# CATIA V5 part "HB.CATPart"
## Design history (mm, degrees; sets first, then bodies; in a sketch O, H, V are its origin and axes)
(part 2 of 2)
Body1 (main body), material "Aluminium Grey"
  Plane10: type Offset, RefPlane zx-plane, Offset 750
  DatumCurve100 to DatumCurve106
  Sketch13 on Plane10, origin (0, 750, 0), H (-1, 0, 0), V (0, 0, 1)
    projected circle E1 centre (845.606, 208.1688) radius 251.3368 from edge of DatumCurve100
    projected arc E2 centre (845.606, 208.1688) radius 251.3368 from (594.2692, 208.1688) to (704.7658, 0) ccw from edge of DatumCurve100
    projected arc E3 centre (845.606, 208.1688) radius 251.3368 from (986.4462, 0) to (594.2692, 208.1688) ccw from edge of DatumCurve100
    projected line E4 (-1750, 0) -> (1250, 0) from edge of DatumCurve101
    projected circle E5 centre (-1402.6201, 208.1688) radius 251.3368 from edge of DatumCurve102
    projected arc E6 centre (-1402.6201, 208.1688) radius 251.3368 from (-1261.78, 0) to (-1230.798, 24.7366) ccw from edge of DatumCurve102
    projected arc E7 centre (-1402.6201, 208.1688) radius 251.3368 from (-1213.9619, 374.2358) to (-1376.9419, 458.1904) ccw from edge of DatumCurve102
    projected arc E8 centre (-831.0348, -15069.2644) radius 15448.2469 from (493.1505, 322.1249) to (-1213.9619, 374.2358) ccw from edge of DatumCurve103
    projected arc E9 centre (1589.552, -12678.1554) radius 13467.1328 from (1187.0274, 782.9605) to (-1376.9419, 458.1904) ccw from edge of DatumCurve104
    projected line E10 (353.7012, 97.7708) -> (493.1505, 322.1249) from edge of DatumCurve105
    projected arc E11 centre (-2835.5431, 52064.8447) radius 52064.8447 from (-1230.798, 24.7366) to (353.7012, 97.7708) ccw from edge of DatumCurve106
    line L1 (704.7658, 0) -> (-1261.78, 0)
  Point171: (0, -50, 0), relative to vertex [element of Sketch13 | element of Sketch13]
  Point172: (0, -26, 0), relative to vertex [element of Sketch13 | element of Sketch13]
  DatumCurve107 to DatumCurve114
  Point173: (-24, 0, 0), relative to vertex [face of Corner45 | face of Curve64]
  Point174: (27, 6, 75), relative to Point165
  Curve74: Elements (Point174; Point167)
  Curve75: Elements (Point174; Point163)
  Corner50: Element1 Curve74, Element2 Curve75, Radius 48, Direction (0, 0, 1)
  Point175: type OnCurve, Support Corner45, Ratio 0.63
  Point176: type OnCurve, Support Corner45, Ratio 0.94
  Curve76: Elements (Point176; Point163)
  Curve77: Elements (Point175; Point167)
  Split8: ToCut Corner45, Cutting Point176
  Split9: ToCut Project6, Cutting Point148
  Fill43: Boundary ({project ToProject DatumCurve23, Support Plane10, Direction DatumCurve83}; Split8; Curve77; Corner50; Curve76; {split ToCut Corner45, Cutting Point176}; Curve66; Split9)
  Symmetry37: ToTransfor Fill43, Reference zx-plane
  Point177: (-42, 30, 0), relative to Point141
  DatumPoint4
  Point178: (-60, 0, 0), relative to DatumPoint4
  DatumPoint5
  Point179: (-60, 0, 0), relative to DatumPoint5
  Point180: (-40, 7, 2), relative to Point28
  Line35: type PtPt, FirstPoint Point177, SecondPoint Point178
  Line36: type PtPt, FirstPoint Point178, SecondPoint Point179
  Corner51: Element1 Line36, Element2 Line35, Radius 48, Direction (0, 0, 1)
  DatumCurve115
  Point181: type OnCurve, Support DatumCurve115, Ratio 0.59
  Point182: (-46, 0, 0), relative to Point181
  Curve78: Elements (Point180; Point182; Point179)
  Point183: (31, 0, -20), relative to vertex of DatumCurve17
  Curve79: Elements (Point183; Point180)
  Point184: (-31, 0, 33), relative to Point170
  Curve80: Elements (Point183; Point184; Point170)
  Line37: type PtPt, FirstPoint Point168, SecondPoint Point177
  Fill44: Boundary (Line37; Corner49; Curve80; Curve79; Curve78; Corner51)
  Symmetry38: ToTransfor Fill44, Reference zx-plane
  Line38: type PtPt, FirstPoint Point141, SecondPoint Point177
  Line39: type PtPt, FirstPoint Point168, SecondPoint Point141
  Fill45: Boundary (Line37; Line38; Line39)
  Point185: type OnCurve, Support Corner48, Ratio 0.47
  Point186: (-32, 31, -24), relative to Point185
  Point187: (-32, 31, -16), relative to Point161
  Point188: (-32, 31, -3), relative to Point160
  Point189: (-32, 0, 0), relative to Point159
  Curve81: Elements (Point186; Point187; Point188)
  Curve82: Elements (Point189; Point188)
  Corner52: Element1 Curve82, Element2 Curve81, Radius 62, Direction (0, 0, 1)
  Line40: type PtPt, FirstPoint Point159, SecondPoint Point189
  Line41: type PtPt, FirstPoint vertex [face of Curve70 | face of Corner48], SecondPoint vertex [face of Curve81 | face of Corner52]
  Line42: type PtPt, FirstPoint Point186, SecondPoint Point185
  MultiSel8
  Corner53: Element1 {symmetry ToTransfor Corner52, Reference zx-plane}, Element2 Corner52, Radius 500, Direction (0, 0, 1)
  DatumCurve116 to DatumCurve128
  Fill46: Boundary (Corner48; Line41; DatumCurve117; DatumCurve118; DatumCurve119; DatumCurve120; DatumCurve121; {symmetry ToTransfor Line41, Reference zx-plane}; DatumCurve124)
  Fill47: Boundary ({fillboundary BoundaryWire edge of Fill46, Support Fill46}; DatumCurve126; Line42; DatumCurve116)
  Symmetry39: ToTransfor Fill47, Reference zx-plane
  Join10: Elements (Fill47; Fill46; Symmetry39)
  Join11: Elements (edge of Fill46; edge of Fill46; edge of Fill46; edge of Fill46; edge of Symmetry39; edge of Fill46; edge of Fill47)
  Extrapol3: ToExtrapol Join11, Support Join10, Length 34
  Symmetry40: ToTransfor Fill45, Reference zx-plane
  Point190: type OnCurve, Support Corner44, Ratio 0.1935
  Symmetry41: ToTransfor Point190, Reference zx-plane
  Split10: ToCut Corner44, Cutting Point190
  Split11: ToCut Split10, Cutting Symmetry41
  Point191: (-37, 30, 40), relative to Symmetry41
  Point192: (-37, 22, 75), relative to Symmetry29
  Point193: type OnCurve, Support Split11, Ratio 0.5
  Point194: (-50, 0, 100), relative to Point193
  Symmetry42: ToTransfor Point192, Reference zx-plane
  Symmetry43: ToTransfor Point191, Reference zx-plane
  Curve83: Elements (Point191; Point192; Point194; Symmetry42; Symmetry43)
  Line43: type PtPt, FirstPoint Point190, SecondPoint Symmetry43
  Line44: type PtPt, FirstPoint Symmetry41, SecondPoint Point191
  Fill48: Boundary (Split11; Line44; Curve83; Line43)
  Join12: Elements (Symmetry38; Fill44)
  Join13: Elements (edge of Fill44; edge of Fill44; edge of Fill44; edge of Symmetry38; edge of Symmetry38; edge of Symmetry38)
  Point195: (17, 0, 101), relative to Point188
  Point196: (21, 0, 115), relative to Point189
  Symmetry44: ToTransfor Point195, Reference zx-plane
  Curve84: Elements (Point186; Point195; Point196; Symmetry44; vertex of Join11)
  Fill49: Boundary (Join11; Curve84)
  Point197: (-69, 20, 0), relative to vertex [face of Curve74 | face of Corner50]
  Point198: (-51, 20, 0), relative to vertex [face of Corner50 | face of Curve75]
  Point199: (-36, 20, 4), relative to Point167
  Curve85: Elements (Point175; Point199; Point197)
  Point200: (-45, 20, 0), relative to Point163
  Point201: (-62, 20, 0), relative to vertex [face of Corner50 | face of Curve75]
  Curve86: Elements (Point176; Point200; Point201)
  Corner54: Element1 Curve85, Element2 Curve86, Radius 56, Direction (0, 0, 1)
  Fill50: Boundary ({fillboundary BoundaryWire edge of Fill42}; {fillboundary BoundaryWire edge of Fill42}; Corner54)
  Symmetry45: ToTransfor Fill50, Reference zx-plane
  Fill51: Boundary (Corner50; Curve77; Corner54; Curve76)
  Symmetry46: ToTransfor Fill51, Reference zx-plane
  RectPattern1: of Extrapol3, direction 1 instances 5, spacing 22, along Z axis
  Join14: Elements (Fill42; Fill41; Symmetry34)
  Split12: ToCut RectPattern1, Cutting Join14
  Sketch14 on Plane9, origin (0, 0, 0), H (-1, 0, 0), V (0, 0, 1)
    line L1 (-1893.9288, 231.778) -> (-1872.7429, 355.2953)
  RectPattern2: of Join12, direction 1 instances 5, spacing 18, along Sketch14.L1 reversed
  Fill52: Boundary (edge of Fill43; edge of Fill51; edge of Fill51; edge of Fill43; edge of Fill43; {fillboundary BoundaryWire edge of Fill50, Support Fill50}; edge of Fill50)
  Symmetry47: ToTransfor Fill52, Reference zx-plane
  Plane11: type Offset, RefPlane yz-plane, Offset -1983, reversed
  Sketch15 on Plane11, origin (1983, 0, 0), H (0, 1, 0), V (0, 0, 1)
    arc A1 centre (579.7144, -6029.5397) radius 6143.2661 from (348.4449, 109.3717) to (631.5314, 113.5079) cw
    arc A2 centre (578.747, -7048.2125) radius 7181.3825 from (337.5808, 129.1194) to (658.2496, 132.7299) cw
    arc A3 centre (498.876, -4576.5398) radius 4728.1195 from (331.838, 148.6282) to (667.528, 148.5708) cw
    arc A4 centre (459.6706, -4602.659) radius 4771.8397 from (330.2171, 167.4244) to (670.7479, 164.51) cw
    arc A5 centre (67.7258, -10855.4937) radius 11063.6268 from (371.8413, 203.9526) to (666.0962, 191.94) cw
    arc A6 centre (371.2568, 313.1531) radius 109.2021 from (340.512, 208.3683) to (371.8413, 203.9526) ccw
    arc A7 centre (1244.1204, 15142.2871) radius 14945.9617 from (378.9979, 221.3845) to (655.0631, 207.938) ccw
    arc A8 centre (381.8374, 303.895) radius 82.5593 from (378.9979, 221.3845) to (353.3079, 226.4217) cw
    arc A9 centre (664.9631, 3780.43) radius 3557.7008 from (631.3203, 222.8883) to (395.5709, 232.9431) cw
    arc A10 centre (404.1283, 319.2931) radius 86.7729 from (395.5709, 232.9431) to (369.4376, 239.7563) cw
    arc A11 centre (276.8632, -8315.0864) radius 8502.6225 from (670.0375, 178.4408) to (332.6514, 187.3531) ccw
  Sketch16 on Plane11, origin (1983, 0, 0), H (0, 1, 0), V (0, 0, 1)
    arc A1 centre (-579.7144, -6029.5397) radius 6143.2661 from (-631.5314, 113.5079) to (-348.4449, 109.3717) cw
    arc A2 centre (-498.876, -4576.5398) radius 4728.1195 from (-667.528, 148.5708) to (-331.838, 148.6282) cw
    arc A3 centre (-578.747, -7048.2125) radius 7181.3825 from (-658.2496, 132.7299) to (-337.5808, 129.1194) cw
    arc A4 centre (-459.6706, -4602.659) radius 4771.8397 from (-670.7479, 164.51) to (-330.2171, 167.4244) cw
    arc A5 centre (-276.8632, -8315.0864) radius 8502.6225 from (-670.0375, 178.4408) to (-332.6514, 187.3531) cw
    arc A6 centre (-67.7258, -10855.4937) radius 11063.6268 from (-666.0962, 191.94) to (-371.8413, 203.9526) cw
    arc A7 centre (-1244.1204, 15142.2871) radius 14945.9617 from (-378.9979, 221.3845) to (-655.0631, 207.938) cw
    arc A8 centre (-664.9631, 3780.43) radius 3557.7008 from (-395.5709, 232.9431) to (-631.3203, 222.8883) cw
    arc A9 centre (-371.2568, 313.1531) radius 109.2021 from (-340.512, 208.3683) to (-371.8413, 203.9526) cw
    arc A10 centre (-381.8374, 303.895) radius 82.5593 from (-353.3079, 226.4217) to (-378.9979, 221.3845) cw
    arc A11 centre (-404.1283, 319.2931) radius 86.7729 from (-369.4376, 239.7563) to (-395.5709, 232.9431) cw
  DatumCurve129
  Project8: ToProject Sketch15, Support Fill52, Direction DatumCurve129
  DatumCurve130
  Project9: ToProject Sketch16, Support Symmetry47, Direction DatumCurve130
  Point202: type OnSurface, Support Fill50, Length 61.277, Direction (-0.6054, 0.7899, 0.0977)
  Point203: (-400, 200, 400), relative to Point202
  Line45: type PtPt, FirstPoint Point203, SecondPoint vertex of Project8
  DatumCurve131 to DatumCurve138
  Extrude1: Element1 DatumCurve137, Lim1 30, Lim2 0, Direction Line45
  Symmetry48: ToTransfor Extrude1, Reference zx-plane
  Extrude2: Element1 DatumCurve136, Lim1 30, Lim2 0, Direction Line45
  Extrude3: Element1 DatumCurve135, Lim1 30, Lim2 0, Direction Line45
  Extrude4: Element1 DatumCurve138, Lim1 30, Lim2 0, Direction Line45
  Plane12: type OffsetPt, RefPlane xy-plane, RefPoint vertex of Project8
  Symmetry49: ToTransfor Line45, Reference Plane12
  Extrude5: Element1 DatumCurve134, Lim1 72, Lim2 0, Direction Symmetry49
  Extrude6: Element1 DatumCurve133, Lim1 88, Lim2 0, Direction Symmetry49
  Extrude7: Element1 DatumCurve132, Lim1 72, Lim2 0, Direction Symmetry49
  Extrude8: Element1 DatumCurve131, Lim1 72, Lim2 0, Direction Symmetry49
  MultiSel9
  Sketch17 on Plane11, origin (1983, 0, 0), H (0, 1, 0), V (0, 0, 1)
    arc A1 centre (476.6529, 174.7692) radius 81.8971 from (521.5443, 243.2666) to (500.4592, 96.4085) cw
    arc A2 centre (580.0907, 169.6044) radius 71.3723 from (603.9034, 102.3217) to (622.598, 226.9379) ccw
    arc A3 centre (415.8776, 176.557) radius 90.5973 from (456.2523, 95.4537) to (470.0326, 249.187) ccw
    arc A4 centre (528.7408, 172.2145) radius 77.5015 from (549.0097, 97.4103) to (567.6868, 239.2197) ccw
    arc A5 centre (348.039, 181.6448) radius 103.4461 from (419.6634, 256.2843) to (403.4064, 94.2631) cw
  DatumCurve139
  Project10: ToProject Sketch17, Support Fill52, Direction DatumCurve139
  Sketch18 on Plane12, origin (0, 0, 187.3531), H (1, 0, 0), V (0, 1, 0)
    projected line E1 (1362.9892, 766.5457) -> (1889.4524, 332.6514) from Line45
  Extrude9: Element1 Project10, Lim1 72, Lim2 9, Direction Sketch18
  Symmetry50: ToTransfor Extrude9, Reference zx-plane
  DatumSurface1
  DatumSurface2
  DatumCurve140 to DatumCurve148
  Join15: Elements (DatumCurve140; DatumCurve141; DatumCurve142; DatumCurve143; DatumCurve144; edge of Fill40; DatumCurve145; DatumCurve146; DatumCurve147; DatumCurve148)
  Extrude10: Element1 Join15, Lim1 72, Lim2 0, Direction (1, 0, 0)
  Fill53: Boundary (edge of Extrude10; edge of Extrude10; edge of Extrude10; edge of Extrude10; edge of Extrude10; edge of Extrude10; edge of Extrude10; edge of Extrude10; edge of Extrude10; edge of Extrude10)
  Split13: ToCut Join12, Cutting Extrude10
  Symmetry51: ToTransfor Extrude10, Reference zx-plane
  Split14: ToCut Split13, Cutting Symmetry51
  Symmetry52: ToTransfor Fill53, Reference zx-plane
  DatumCurve149
  DatumCurve150
  Fill54: Boundary (edge of Extrude10; edge of Extrude10; edge of Extrude10; edge of Fill2; edge of Fill2; edge of Fill2; edge of Symmetry51; DatumCurve149; DatumCurve150; edge of Symmetry34; edge of Symmetry34; edge of Fill41; edge of Fill42; edge of Fill42), Constraint vertex [face of RectPattern2 | face of RectPattern2]
  Sketch19 on Plane11, origin (1983, 0, 0), H (0, 1, 0), V (0, 0, 1)
    unspec C1
    unspec C2
    unspec C3
    unspec C4
    unspec C5
    unspec C6
    unspec C7
    unspec C8
    unspec C9
    line L1 (2.1616, 386.125) -> (-2.1616, 386.1252)
    unspec C10
    unspec C11
    unspec C12
    unspec C13
    arc A1 centre (345.3151, 434.9475) radius 111.0293 from (315.3064, 328.0505) to (273.3903, 350.3643) cw
    arc A2 centre (150.7383, 206.1261) radius 189.3361 from (273.3903, 350.3643) to (247.2342, 369.027) ccw
    arc A3 centre (220.0018, 323.0542) radius 53.4331 from (247.2342, 369.027) to (220.3303, 376.4863) ccw
    arc A4 centre (26.5283, 2421.0838) radius 2053.7619 from (220.3303, 376.4863) to (94.5381, 368.4482) cw
    line L2 (75.2525, 361.6987) -> (69.5021, 357.4156)
    line L3 (48.2309, 350.3643) -> (0, 350.3643)
    arc A5 centre (48.2309, 385.9736) radius 35.6093 from (69.5021, 357.4156) to (48.2309, 350.3643) cw
    arc A6 centre (95.6699, 334.2869) radius 34.1801 from (94.5381, 368.4482) to (75.2525, 361.6987) ccw
    line L4 (-48.2309, 350.3643) -> (0, 350.3643)
    arc A7 centre (-48.2309, 385.9736) radius 35.6093 from (-69.5021, 357.4156) to (-48.2309, 350.3643) ccw
    arc A8 centre (-95.6699, 334.2869) radius 34.1801 from (-94.5381, 368.4482) to (-75.2525, 361.6987) cw
    line L5 (-75.2525, 361.6987) -> (-69.5021, 357.4156)
    arc A9 centre (-26.5283, 2421.0838) radius 2053.7619 from (-220.3303, 376.4863) to (-94.5381, 368.4482) ccw
    arc A10 centre (-345.3151, 434.9475) radius 111.0293 from (-315.3064, 328.0505) to (-273.3903, 350.3643) ccw
    arc A11 centre (-150.7383, 206.1261) radius 189.3361 from (-273.3903, 350.3643) to (-247.2342, 369.027) cw
    arc A12 centre (-220.0018, 323.0542) radius 53.4331 from (-247.2342, 369.027) to (-220.3303, 376.4863) cw
    arc A13 centre (584.5436, -386.6935) radius 763.772 from (315.3064, 328.0505) to (231.3058, 290.4849) ccw
    arc A14 centre (169.0264, 409.8782) radius 134.6605 from (231.3058, 290.4849) to (192.4523, 277.2709) cw
    arc A15 centre (13.9517, 1732.8423) radius 1466.4756 from (192.4523, 277.2709) to (91.058, 268.3952) cw
    line L6 (77.3882, 272.531) -> (71.9048, 276.6153)
    line L7 (66.5062, 278.4049) -> (0, 278.4049)
    arc A16 centre (66.5062, 269.3673) radius 9.0376 from (71.9048, 276.6153) to (66.5062, 278.4049) ccw
    arc A17 centre (89.9521, 289.3988) radius 21.0327 from (91.058, 268.3952) to (77.3882, 272.531) cw
    line L8 (-77.3882, 272.531) -> (-71.9048, 276.6153)
    arc A18 centre (-66.5062, 269.3673) radius 9.0376 from (-71.9048, 276.6153) to (-66.5062, 278.4049) cw
    line L9 (-66.5062, 278.4049) -> (0, 278.4049)
    arc A19 centre (-89.9521, 289.3988) radius 21.0327 from (-91.058, 268.3952) to (-77.3882, 272.531) ccw
    arc A20 centre (-13.9517, 1732.8423) radius 1466.4756 from (-192.4523, 277.2709) to (-91.058, 268.3952) ccw
    arc A21 centre (-169.0264, 409.8782) radius 134.6605 from (-231.3058, 290.4849) to (-192.4523, 277.2709) ccw
    arc A22 centre (-584.5436, -386.6935) radius 763.772 from (-315.3064, 328.0505) to (-231.3058, 290.4849) cw
  DatumCurve151
  DatumCurve152
  Project11: ToProject Sketch19, Support Fill54, Direction DatumCurve152
  Split15: ToCut Fill54, Cutting Project11
  RectPattern3: of Split14, direction 1 instances 2, spacing 13, along Sketch14.L1
  Translate1: ToTransfor Split14, Direction Sketch14, Length -3
  Split16: ToCut RectPattern2, Cutting Split15
  Split17: ToCut RectPattern3, Cutting Fill2
  Split18: ToCut Split17, Cutting Extrude10
  Split19: ToCut Split18, Cutting Symmetry51
  Join16: Elements (Fill4; Fill3; Fill2; Symmetry7; Symmetry8)
  Split20: ToCut Split16, Cutting Split15
  Join17: Elements edge of Fill25
  Join18: Elements edge of Fill20
  Corner55: Element1 Join17, Element2 Join18, Radius 800, Direction (0, 0, 1)
  Join19: Elements edge of Fill25
  Split21: ToCut Join19, Cutting vertex [face of Fill25 | face of Corner55]
  Join20: Elements edge of Fill20
  Split22: ToCut Join20, Cutting vertex [face of Corner55 | face of Fill20]
  Fill55: Boundary ({fillboundary BoundaryWire Split21, Support Split3}; Corner55; Split22)
  Symmetry53: ToTransfor Fill55, Reference zx-plane
  Join21: Elements (Fill55; Split3)
  Join22: Elements (Symmetry53; Join21)
  Point204: type OnCurve, Support edge of Fill4, Ratio 0.953
  Line46: type PtPt, FirstPoint vertex [face of Extrapol1], SecondPoint Point204
  Fill56: Boundary (Line46; edge of Split6; edge of Split6; edge of Split6; edge of Extrude10; edge of Extrude10; edge of Extrude10; edge of Fill4; edge of Fill4; edge of Fill4)
  Symmetry54: ToTransfor Fill56, Reference zx-plane
  Sketch20 on Plane11, origin (1983, 0, 0), H (0, 1, 0), V (0, 0, 1)
    arc A1 centre (584.4682, 462.3739) radius 44.6302 from (542.1248, 476.4768) to (542.5396, 447.0818) ccw
    arc A2 centre (444.2457, 610.8286) radius 204.2085 from (534.8246, 427.8078) to (493.2845, 412.5956) cw
    line L1 (469.231, 414.1503) -> (452.3848, 420.7155)
    line L2 (514.8876, 472.5555) -> (514.322, 472.172)
    arc A3 centre (-36.5724, 913.4188) radius 705.8211 from (506.72, 462.845) to (514.322, 472.172) ccw
    unspec C1
    unspec C2
    arc A4 centre (537.6077, 532.2395) radius 51.7217 from (536.2664, 480.5352) to (540.0286, 480.5745) ccw
    unspec C3
    arc A5 centre (527.9239, 441.7511) radius 15.5575 from (534.8246, 427.8078) to (542.5396, 447.0818) ccw
    arc A6 centre (483.7094, 451.3019) radius 39.8731 from (493.2845, 412.5956) to (469.231, 414.1503) cw
    arc A7 centre (438.2473, 384.4706) radius 38.9045 from (452.3848, 420.7155) to (433.414, 423.0737) ccw
    arc A8 centre (550.6224, 473.0151) radius 9.1756 from (542.1248, 476.4768) to (545.8464, 480.8498) cw
    arc A9 centre (545.7335, 481.0352) radius 0.217 from (545.8464, 480.8498) to (545.6912, 481.248) ccw
    arc A10 centre (433.392, 423.2498) radius 0.1775 from (433.414, 423.0737) to (433.345, 423.4209) cw
  DatumCurve153
  MultiSel10
  Join23: Elements (edge of MultiSel10; edge of MultiSel10; edge of MultiSel10; edge of MultiSel10; edge of MultiSel10; edge of MultiSel10; edge of MultiSel10)
  Extrapol4: ToExtrapol Join23, Support {translate ToTransfor Fill56, Direction DatumCurve153, Length 21}, Length 9.6
  Symmetry55: ToTransfor Join23, Reference zx-plane
  Extrapol5: ToExtrapol Symmetry55, Support {translate ToTransfor Symmetry54, Direction DatumCurve153, Length 21}, Length 9.6
  DatumCurve154
  Project12: ToProject Sketch20, Support Extrapol4, Direction DatumCurve154
  DatumCurve155
  Extrude11: Element1 Project12, Lim1 72, Lim2 18, Direction DatumCurve155
  Symmetry56: ToTransfor Extrude11, Reference zx-plane
  Trim1: Trimmed (Extrapol4; Extrude11)
  Trim2: Trimmed (Extrapol5; Symmetry56)
  Extrude12: Element1 Project12, Lim1 15, Lim2 73, Direction (1, 0, 0)
  Symmetry57: ToTransfor Extrude12, Reference zx-plane
  Fill57: Boundary (edge of Extrude12; edge of Extrude12; edge of Extrude12; edge of Extrude12; edge of Extrude12; edge of Extrude12; edge of Extrude12; edge of Extrude12; edge of Extrude12; edge of Extrude12; edge of Extrude12; edge of Extrude12; edge of Extrude12; edge of Extrude12; edge of Extrude12; edge of Extrude12; edge of Extrude12; edge of Extrude12; edge of Extrude12; edge of Extrude12; edge of Extrude12; edge of Extrude12)
  Symmetry58: ToTransfor Fill57, Reference zx-plane
  Sketch21 on Plane11, origin (1983, 0, 0), H (0, 1, 0), V (0, 0, 1)
    line L1 (534.382, 447.2411) -> (534.382, 462.5715)
    line L2 (529.5836, 466.6031) -> (523.3235, 465.5076)
    arc A1 centre (434.8656, 529.043) radius 104.3311 from (512.7449, 459.6183) to (475.1551, 432.8051) cw
    line L3 (475.1686, 430.531) -> (483.713, 427.0726)
    line L4 (506.2355, 426.9164) -> (525.6356, 434.4574)
    arc A2 centre (530.2891, 462.5715) radius 4.0929 from (529.5836, 466.6031) to (534.382, 462.5715) cw
    arc A3 centre (526.5, 447.3564) radius 18.427 from (512.7449, 459.6183) to (523.3235, 465.5076) cw
    arc A4 centre (475.6299, 431.6708) radius 1.2296 from (475.1551, 432.8051) to (475.1686, 430.531) ccw
    arc A5 centre (495.1711, 455.3808) radius 30.5392 from (483.713, 427.0726) to (506.2355, 426.9164) ccw
    arc A6 centre (520.6665, 447.2411) radius 13.7155 from (525.6356, 434.4574) to (534.382, 447.2411) ccw
  Project13: ToProject Sketch21, Support Fill56, Direction (1, 0, 0)
  Fill58: Boundary Project13
  Translate2: ToTransfor Fill58, Direction (1, 0, 0), Length -49
  Translate3: ToTransfor Project13, Direction (1, 0, 0), Length -49
  Extrude13: Element1 Translate3, Lim1 35, Lim2 0, Direction (1, 0, 0)
  Join24: Elements (Translate2; Extrude13)
  Symmetry59: ToTransfor Join24, Reference zx-plane
  RectPattern4: of Fill57, direction 1 instances 2, spacing 88, along X axis
  Symmetry60: ToTransfor RectPattern4, Reference zx-plane
  Line47: type PtPt, FirstPoint vertex [face of Symmetry19 | face of Fill24], SecondPoint vertex [face of Fill30]
  DatumCurve156
  Fill59: Boundary (DatumCurve156; edge of Symmetry19; edge of Symmetry19; edge of MultiSel5; Line47; edge of Symmetry19)
  DatumCurve157
  DatumSurface3
  Boundary1: Boundary DatumSurface3
  Point205: type OnCurve, Support Boundary1, RefPoint {extremum Reference Boundary1, Direction (1, 2, 3)}, Ratio 0.19
  DatumSurface4
  Plane13: type Tangent, Support DatumSurface4, RefPoint Point205
  Line48: type PtDir, RefPoint Point205, Direction Plane13, Start -87, End 20
  Extrude14: Element1 Boundary1, Lim1 35, Lim2 0, Direction Line48
  Fill60: Boundary edge of Extrude14
  MultiSel11
  Translate4: ToTransfor Fill59, Direction Line48, Length -36
  Join25: Elements (edge of Translate4; edge of Translate4; edge of Translate4)
  Extrapol6: ToExtrapol Join25, Support Translate4, Length 67
  Sketch22 on Plane8, origin (-1447, 0, 0), H (0, 1, 0), V (0, 0, 1)
    line L1 (0, 465.1008) -> (0, 764.1366)
  Project14: ToProject Sketch22, Support Extrapol6, Direction (1, 0, 0)
  Split23: ToCut Extrapol6, Cutting Project14
  Symmetry61: ToTransfor Split23, Reference zx-plane
  DatumPoint6
  Line49: type PtPt, FirstPoint vertex of Join25, SecondPoint DatumPoint6
  Split24: ToCut Join25, Cutting edge of Symmetry61
  Line50: type PtPt, FirstPoint vertex of Split24, SecondPoint vertex [face of Fill30]
  Fill61: Boundary (Line50; edge of MultiSel5; edge of Symmetry19; edge of Symmetry19; Line49; Split24)
  Symmetry62: ToTransfor Fill61, Reference zx-plane
  Sketch23 on Plane13, origin (-400.5776, -753.3763, 758.3765), H (0.8829, -0.4695, 0), V (0.3119, 0.5866, 0.7474)
    unspec C1
    unspec C2
    line L1 (-550.2617, -107.4617) -> (-496.071, -100.5537)
    arc A1 centre (-228.6419, -1366.8911) radius 1289.9891 from (-495.357, -104.7758) to (-675.1371, -156.6375) ccw
    arc A2 centre (-715.5789, 39.4428) radius 210.9571 from (-810.3894, -149.0085) to (-908.7775, -45.2755) cw
    arc A3 centre (-733.9816, 2.8643) radius 170.0103 from (-675.1371, -156.6375) to (-810.3894, -149.0085) cw
    arc A4 centre (-1072.7336, -116.4617) radius 178.743 from (-908.7775, -45.2755) to (-941.6747, 5.081) ccw
    arc A5 centre (-495.8, -102.6793) radius 2.1428 from (-495.357, -104.7758) to (-496.071, -100.5537) ccw
    arc A6 centre (-941.1153, 5.5998) radius 0.7629 from (-941.6747, 5.081) to (-940.636, 6.1933) cw
  Project15: ToProject Sketch23, Support Split23, Direction Line48
  Symmetry63: ToTransfor Project15, Reference zx-plane
  Split25: ToCut Split23, Cutting Project15
  Split26: ToCut Symmetry61, Cutting Symmetry63
  Extrude15: Element1 Project15, Lim1 35, Lim2 5, Direction Line48
  Fill62: Boundary (edge of Extrude15; edge of Extrude15; edge of Extrude15; edge of Extrude15; edge of Extrude15; edge of Extrude15; edge of Extrude15; edge of Extrude15; edge of Extrude15)
  MultiSel12
  Fill63: Boundary (edge of Extrude15; edge of Extrude15; edge of Extrude15; edge of Extrude15; edge of Extrude15; edge of Extrude15; edge of Extrude15; edge of Extrude15; edge of Extrude15)
  Symmetry64: ToTransfor Fill63, Reference zx-plane
  Point206: (-41, 0, -40), relative to vertex [face of Symmetry19 | face of Fill24]
  Point207: type OnCurve, Support edge of Fill24, Ratio 0.42
  Point208: type OnCurve, Support edge of Fill24, Ratio 0.68
  Point209: type OnCurve, Support edge of Fill24, Ratio 0.82
  Point210: type OnCurve, Support edge of Fill24, Ratio 0.24
  Point211: (-41, 0, -40), relative to Point210
  Point212: (-36, 0, -48), relative to Point207
  Point213: (-23, 0, -47), relative to Point208
  Point214: (21, 18, -26), relative to vertex [face of Fill23]
  Curve87: Elements (Point211; Point212; Point213; vertex [face of Fill23])
  Symmetry65: ToTransfor Point211, Reference zx-plane
  Curve88: Elements (Symmetry65; Point206; Point211)
  Symmetry66: ToTransfor Curve87, Reference zx-plane
  Corner56: Element1 Curve88, Element2 Symmetry66, Radius 235, Direction (0, 0, 1)
  Corner57: Element1 Corner56, Element2 Curve87, Radius 235, Direction (0, 0, 1)
  Point215: (52, 23, -26), relative to vertex [face of Fill23]
  Curve89: Elements (Point215; vertex of Curve87)
  RectPattern5: of Split14, direction 1 instances 2, spacing 11, along Sketch14.L1
  Translate5: ToTransfor Split14, Direction Sketch14, Length -3
  Split27: ToCut Split20, Cutting Split15
  Split28: ToCut RectPattern5, Cutting Fill2
  Split29: ToCut Split28, Cutting Extrude10
  Split30: ToCut Split29, Cutting Symmetry51
  Symmetry67: ToTransfor Curve89, Reference zx-plane
  Sketch24 on zx-plane, origin (0, 0, 0), H (-1, 0, 0), V (0, 0, 1)
    arc A1 centre (866.4137, 384.3689) radius 470.5096 from (1336.5724, 366.199) to (1248.8116, 110.2318) cw
    line L1 (1137.6017, 53.1222) -> (1046.1576, 53.1222)
    point P3 (1046.1576, 53.1222)
    arc A2 centre (1137.6017, 189.957) radius 136.8348 from (1248.8116, 110.2318) to (1137.6017, 53.1222) cw
    arc A3 centre (1348.3431, 534.5006) radius 28.4581 from (1367.979, 555.0989) to (1374.1705, 522.5505) cw
    arc A4 centre (1746.3142, 350.364) radius 410.0476 from (1374.1705, 522.5505) to (1336.5724, 366.199) ccw
  Line51: type PtPt, FirstPoint Point215, SecondPoint Sketch24.P3
  Plane14: type Offset, RefPlane zx-plane, Offset 334
  Sketch25 on Plane14, origin (0, 334, 0), H (-1, 0, 0), V (0, 0, 1)
    arc A1 centre (558.6644, 515.4591) radius 768.3663 from (1311.3624, 361.0812) to (1219.3832, 123.2378) cw
    arc A2 centre (1096.2214, 196.3501) radius 143.2279 from (1219.3832, 123.2378) to (1165.8532, 71.1877) cw
    arc A3 centre (1302.6643, 490.7491) radius 46.7602 from (1344.7783, 511.0697) to (1345.8013, 472.7017) cw
    arc A4 centre (1902.2854, 239.8832) radius 603.2238 from (1345.8013, 472.7017) to (1311.3624, 361.0812) ccw
    line L1 (1060.6591, 57.831) -> (1114.371, 57.831)
    arc A5 centre (1114.371, 163.7264) radius 105.8954 from (1165.8532, 71.1877) to (1114.371, 57.831) cw
  Symmetry68: ToTransfor Sketch25, Reference zx-plane
  Curve90: Elements (vertex [face of Symmetry68 | face of Symmetry68]; vertex [element of Sketch24 | element of Sketch24]; vertex [element of Sketch25 | element of Sketch25])
  Curve91: Elements (vertex [face of Symmetry68 | face of Symmetry68]; vertex [element of Sketch24 | element of Sketch24]; vertex [element of Sketch25 | element of Sketch25])
  Curve92: Elements (vertex [face of Symmetry68 | face of Symmetry68]; vertex [element of Sketch24 | element of Sketch24]; vertex [element of Sketch25 | element of Sketch25])
  Curve93: Elements (vertex [face of Symmetry68 | face of Symmetry68]; vertex [element of Sketch24 | element of Sketch24]; vertex [element of Sketch25 | element of Sketch25])
  Fill64: Boundary (Symmetry68; Corner57; Sketch25; Curve90)
  Fill65: Boundary (Symmetry68; Curve91; {fillboundary BoundaryWire Sketch25}; {fillboundary BoundaryWire edge of Fill64, Support Fill64})
  Fill66: Boundary (Symmetry68; {fillboundary BoundaryWire edge of Fill65, Support Fill65}; Sketch25; Curve92)
  Symmetry69: ToTransfor Line51, Reference zx-plane
  Fill67: Boundary (Symmetry68; {fillboundary BoundaryWire edge of Fill66, Support Fill66}; Sketch25; Curve93)
  Fill68: Boundary (Symmetry68; Symmetry69; Line51; Sketch25; {fillboundary BoundaryWire edge of Fill67, Support Fill67})
  Fill69: Boundary ({fillboundary BoundaryWire edge of Fill64, Support Fill64}; {fillboundary BoundaryWire edge of Fill65, Support Fill65}; {fillboundary BoundaryWire edge of Fill66, Support Fill66}; {fillboundary BoundaryWire edge of Fill67, Support Fill67}; {fillboundary BoundaryWire edge of Fill68, Support Fill68}; Line51; Curve89; Corner57)
  Symmetry70: ToTransfor Fill69, Reference zx-plane
  Join26: Elements (Fill69; Fill65; Fill64; Fill66; Fill67; Fill68; Symmetry70)
  Join27: Elements (Corner57; Curve89; Symmetry67)
  Extrude16: Element1 Join27, Lim1 29, Lim2 0, Direction (1, 0, 0)
  Join28: Elements (Join26; Extrude16)
  Fillet1: radius 15, on edge [face of Extrude16 | face of Fill69]
  Point216: type OnCurve, Support edge of Extrude16, Ratio 0.5
  Line52: type PtPt, FirstPoint Point216, SecondPoint vertex [face of Symmetry19 | face of Fill24]
  Point217: type OnCurve, Support edge of Fillet1, Ratio 0.14
  Line53: type PtPt, FirstPoint Point217, SecondPoint vertex [face of Fill23]
  Fill70: Boundary (Line53; edge of Fill23; edge of Fill24; Line52; edge of Extrude16)
  Translate6: ToTransfor Fill70, Direction (1, 0, 0), Length 12
  Join29: Elements (edge of Translate6; edge of Translate6; edge of Translate6; edge of Translate6)
  Extrapol7: ToExtrapol Join29, Support Translate6, Length 5
  Symmetry71: ToTransfor Extrapol7, Reference zx-plane
  Join30: Elements (Symmetry71; Extrapol7)
  Fillet2: radius 1500, on edge [face of Translate6 | face of Symmetry71]
  Extrude17: Element1 edge of Extrude16, Lim1 12, Lim2 0, Direction (1, 0, 0)
  Join31: Elements (Extrude17; Fillet1)
  Join32: Elements (Symmetry28; Split7; Symmetry10; Symmetry21; Join6; Fill6; Split6; Fill40)
  Join33: Elements (Fill30; Fill28; Fill12; Join2; Join16; Symmetry12; Symmetry13; Symmetry22; {symmetry ToTransfor Fill30, Reference zx-plane}; {symmetry ToTransfor Fill29, Reference zx-plane}; Fill29)
  Join34: Elements (Join4; Symmetry16; Symmetry15; Join3)
  Healing1: BodyToHeal Join32, TangencyAngle 0.5, SharpnessAngle 0.5
  Healing2: BodyToHeal Join33, TangencyAngle 0.5, SharpnessAngle 0.5
  Healing3: BodyToHeal Join22, TangencyAngle 0.5, SharpnessAngle 0.5
  Set2
    DatumSurface5 to DatumSurface32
